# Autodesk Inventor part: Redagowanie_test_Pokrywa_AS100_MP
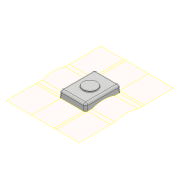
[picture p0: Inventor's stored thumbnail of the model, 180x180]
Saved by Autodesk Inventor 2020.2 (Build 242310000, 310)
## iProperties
Created: 2015-11
Part Number: Redagowanie_test_Pokrywa_AS100_MP
Material: Ogólne
Document SubType Name: Modeling
Designer: F.Stasiak
Density: 1 g/cm^3
Appearance: Domyślne
Catalog Web Link: www.expertbooks.pl
Manager: www.cadconsulting.pl
Company: Fabian Stasiak CAD Consulting
Author: F.Stasiak
Subject: Zbiór ćwiczeń. Autodesk Inventor 2020. Kurs Professional
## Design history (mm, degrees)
derived "Pokrywa_AS100.ipt"
node "Redagowanie_test_Pokrywa_AS100_WP"
node "Płaszczyzna konstrukcyjna1"
node "Podział1" dims "Xmax" = 54, "Xmin" = -54, "Ymax" = 70, "Ymin" = -70, "Zmax" = 16, "Zmin" = -19
node "Podział2" dims "Xmax" = 54, "Xmin" = -54, "Ymax" = 70, "Ymin" = -70, "Zmax" = 16, "Zmin" = -19
node "Podział3" dims "Xmax" = 54, "Xmin" = -54, "Ymax" = 70, "Ymin" = -70, "Zmax" = 16, "Zmin" = -19
node "Podział4" dims "Xmax" = 54, "Xmin" = -54, "Ymax" = 70, "Ymin" = -70, "Zmax" = 16, "Zmin" = -19
node "Podział5" dims "Xmax" = 54, "Xmin" = -54, "Ymax" = 70, "Ymin" = -70, "Zmax" = 16, "Zmin" = -19
node "Podział6" dims "Xmax" = 54, "Xmin" = -54, "Ymax" = 70, "Ymin" = -70, "Zmax" = 16, "Zmin" = -19
node "Podział7" dims "Xmax" = 54, "Xmin" = -54, "Ymax" = 70, "Ymin" = -70, "Zmax" = 16, "Zmin" = -19
node "Podział8" dims "Xmax" = 54, "Xmin" = -54, "Ymax" = 70, "Ymin" = -70, "Zmax" = 16, "Zmin" = -19
node "Podział9" dims "Xmax" = 54, "Xmin" = -54, "Ymax" = 70, "Ymin" = -70, "Zmax" = 16, "Zmin" = -19
node "Podział10" dims "Xmax" = 54, "Xmin" = -54, "Ymax" = 70, "Ymin" = -70, "Zmax" = 16, "Zmin" = -19
node "Podział11" dims "Xmax" = 54, "Xmin" = -54, "Ymax" = 70, "Ymin" = -70, "Zmax" = 16, "Zmin" = -19
node "Podział12" dims "Xmax" = 54, "Xmin" = -54, "Ymax" = 70, "Ymin" = -70, "Zmax" = 16, "Zmin" = -19
node "Podział13" dims "Xmax" = 54, "Xmin" = -54, "Ymax" = 70, "Ymin" = -70, "Zmax" = 16, "Zmin" = -19
node "Podział14" dims "Xmax" = 54, "Xmin" = -54, "Ymax" = 70, "Ymin" = -70, "Zmax" = 16, "Zmin" = -19
node "Podział15" dims "Xmax" = 54, "Xmin" = -54, "Ymax" = 70, "Ymin" = -70, "Zmax" = 16, "Zmin" = -19
node "Podział16" dims "Xmax" = 54, "Xmin" = -54, "Ymax" = 70, "Ymin" = -70, "Zmax" = 16, "Zmin" = -19
feature "Oddzielenie matrycy2"
feature "Bryła1::Pokrywa_AS100.ipt"
tag "Bryła wyprowadzona1"
feature "Bryła1::Redagowanie_test_Pokrywa_AS100_WP"
tag "Bryła wyprowadzona2"
node "Bryła5"
node "Bryła6"
node "Bryła1"
feature "Pokrywa_AS100.ipt_Bodies"
node "Bryła2"
feature "Redagowanie_test_Pokrywa_AS100_WP_Bodies"
feature "Powierzchnia1"
body "Srf2"
feature "Powierzchnia2"
body "Srf3"
feature "Powierzchnia3"
body "Srf4"
feature "Powierzchnia4"
body "Srf5"
feature "Powierzchnia5"
body "Srf6"
feature "Powierzchnia6"
body "Srf7"
feature "Powierzchnia7"
body "Srf8"
feature "Powierzchnia8"
body "Srf9"
feature "Powierzchnia9"
body "Srf10"
feature "Powierzchnia10"
body "Srf11"
feature "Powierzchnia11"
body "Srf12"
feature "Powierzchnia12"
body "Srf13"
feature "Powierzchnia13"
body "Srf14"
feature "Powierzchnia14"
body "Srf15"
feature "Powierzchnia15"
body "Srf16"
feature "Powierzchnia16"
body "Srf17"
other parameters: "d1" = 54, "d2" = 54, "d5" = 35, "d6" = 0
